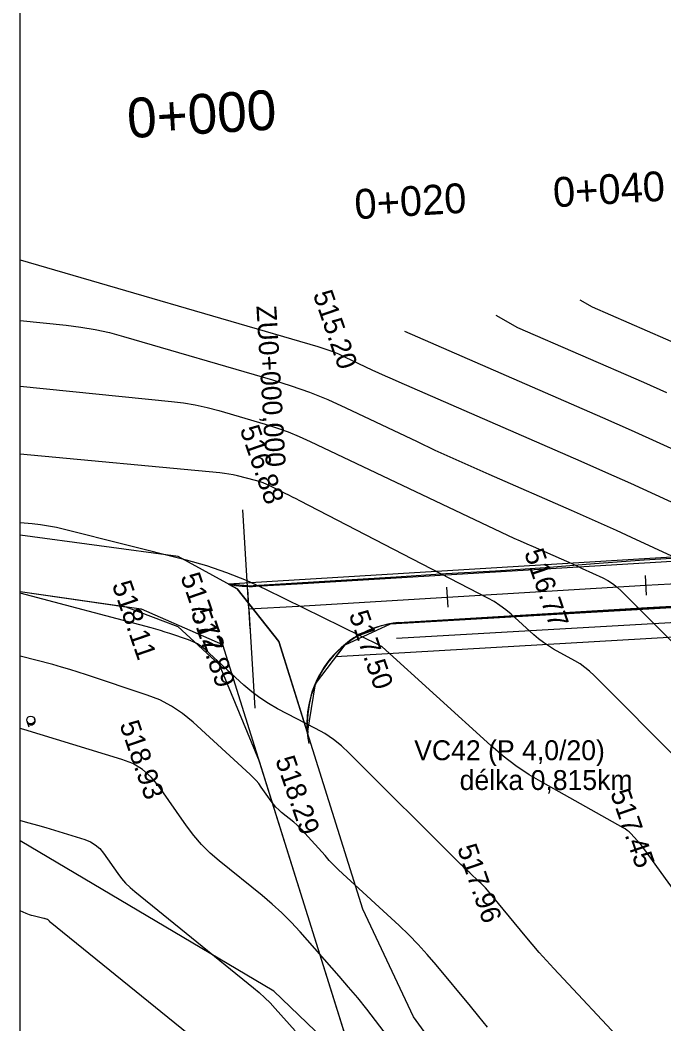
# Model space of a CAD drawing. Extents: x -636600 to -628587, y -1090963 to -1085869.
# Drawn here: x -629847.3 to -629782.5, y -1090868.7 to -1090767.7 of the extents above; entities that cross this region are included whole.
import ezdxf

# ---------------------------------------------------------------- set-up
doc = ezdxf.new("R2010")
doc.units = 0
for name, color, linetype in [('01_PARCELY_NÁVRH_PC', 7, 'Continuous'), ('06_ÚSES_IP_NAVRH', 7, 'Continuous'), ('08_LEGENDA_HV', 7, 'Continuous'), ('21', 7, 'Continuous'), ('42', 7, 'Continuous'), ('43', 7, 'Continuous'), ('Ex_Major Contours', 7, 'Continuous'), ('Ex_Minor Contours', 7, 'Continuous'), ('HEKTOMETRY100', 7, 'Continuous'), ('HEKTOMETRY20', 7, 'Continuous'), ('HL_BODY', 7, 'Continuous'), ('koty_vše', 7, 'Continuous'), ('POLOMERY', 7, 'Continuous'), ('popis', 7, 'Continuous'), ('situace_osa', 7, 'Continuous'), ('situace_těleso', 7, 'Continuous'), ('situace_vozovka', 7, 'Continuous')]:
    doc.layers.add(name, color=color, linetype=linetype)

msp = doc.modelspace()

# ---------------------------------------------------------------- linework, layer by layer
at = {"layer": '01_PARCELY_NÁVRH_PC'}
for points in [[(-629366.45, -1090806.54), (-629540.95, -1090811.44), (-629547.05, -1090811.34), (-629630.75, -1090804.21), (-629643.55, -1090804.77), (-629656.06, -1090806.87), (-629680.19, -1090814.27), (-629692.51, -1090816.32), (-629826.29, -1090824.45), (-629825.42, -1090824.93), (-629821.23, -1090830.23), (-629818.34, -1090839.45), (-629817.55, -1090834.47), (-629814.57, -1090830.54), (-629810, -1090828.44), (-629690.54, -1090821.5), (-629677.85, -1090819.12), (-629655.84, -1090812.08), (-629642.72, -1090809.88), (-629628.47, -1090809.45), (-629558.8, -1090815.77), (-629541.71, -1090816.24), (-629432.05, -1090813.18)], [(-629744.6, -1090962.82), (-629759.09, -1090922.57), (-629763.2, -1090915.17), (-629771.31, -1090905.23), (-629791.75, -1090887), (-629800.69, -1090877.61), (-629807.7, -1090867.98), (-629812.78, -1090857.14), (-629821.23, -1090830.23), (-629825.42, -1090824.93), (-629831.35, -1090821.66), (-629847.27, -1090819.51)], [(-629847.27, -1090825.18), (-629836.62, -1090826.73), (-629831.4, -1090828.72), (-629827.25, -1090832.52), (-629823.21, -1090842.26), (-629813.5, -1090873.3), (-629773.29, -1090911.83), (-629764.97, -1090924.29), (-629750.86, -1090962.82)]]:
    msp.add_lwpolyline(points, dxfattribs=at)
msp.add_lwpolyline([(-629815.5, -1090831.76), (-629814.57, -1090830.54), (-629810, -1090828.44), (-629690.54, -1090821.5), (-629677.85, -1090819.12), (-629655.84, -1090812.08), (-629642.72, -1090809.88), (-629628.47, -1090809.45), (-629558.8, -1090815.77), (-629551.1, -1090815.98), (-629546.74, -1090819.11), (-629558.97, -1090818.77), (-629628.56, -1090812.45), (-629642.43, -1090812.87), (-629655.13, -1090815), (-629677.12, -1090822.03), (-629690.18, -1090824.48)], close=True, dxfattribs=at)
at = {"layer": '06_ÚSES_IP_NAVRH'}
msp.add_lwpolyline([(-629809.39, -1090829.88), (-629689.14, -1090823.02), (-629677.01, -1090820.36), (-629655.14, -1090813.49), (-629637.21, -1090811.06), (-629627.89, -1090811.09), (-629550.85, -1090817.6)], dxfattribs=at)
at = {"layer": '08_LEGENDA_HV'}
msp.add_line((-629847.27, -1090962.82), (-629847.27, -1090665.82), dxfattribs=at)
at = {"layer": '21'}
for p, q in [((-629821.74, -1090865.4), (-629847.27, -1090850.26)), ((-629773.29, -1090911.83), (-629821.74, -1090865.4))]:
    msp.add_line(p, q, dxfattribs=at)
at = {"layer": '42'}
for p, q in [((-629847.27, -1090825.18), (-629835.09, -1090826.95)), ((-629835.09, -1090826.95), (-629826.89, -1090830.51)), ((-629826.89, -1090830.51), (-629814.27, -1090870.83))]:
    msp.add_line(p, q, dxfattribs=at)
at = {"layer": '43'}
for p, q in [((-629846.57, -1090838.25), (-629846.54, -1090838.34)), ((-629846.54, -1090838.34), (-629846.38, -1090838.81))]:
    msp.add_line(p, q, dxfattribs=at)
msp.add_circle((-629846.2, -1090838.12), 0.4, dxfattribs=at)
msp.add_arc((-629846.16, -1090838.21), 0.4, 188.7382, 26.2238, dxfattribs=at)
at = {"layer": 'Ex_Major Contours'}
for points in [[(-629808.6, -1090799.01), (-629788.68, -1090807.7), (-629785.79, -1090808.97), (-629782.91, -1090810.26), (-629780.03, -1090811.57)], [(-629775.18, -1090864), (-629784.52, -1090851.04), (-629784.66, -1090850.85), (-629784.82, -1090850.65), (-629784.98, -1090850.46), (-629785.15, -1090850.28), (-629785.82, -1090849.55), (-629786, -1090849.38), (-629786.19, -1090849.22), (-629786.39, -1090849.08), (-629786.6, -1090848.95), (-629794.66, -1090844.45), (-629796.05, -1090843.62), (-629797.39, -1090842.72), (-629798.67, -1090841.74), (-629799.9, -1090840.69), (-629810.84, -1090830.77), (-629810.86, -1090830.76), (-629810.88, -1090830.74), (-629810.9, -1090830.73), (-629810.92, -1090830.72), (-629811, -1090830.68), (-629811.02, -1090830.67), (-629811.04, -1090830.66), (-629811.06, -1090830.65), (-629811.09, -1090830.63), (-629822.55, -1090824.98), (-629824.49, -1090824.08), (-629826.47, -1090823.3), (-629828.49, -1090822.62), (-629830.54, -1090822.04), (-629842.8, -1090818.96), (-629843.6, -1090818.77), (-629844.42, -1090818.61), (-629845.23, -1090818.49), (-629846.05, -1090818.4), (-629847.27, -1090818.28)], [(-629824.45, -1090874.47), (-629844.23, -1090858.47), (-629844.26, -1090858.45), (-629844.28, -1090858.42), (-629844.3, -1090858.4), (-629844.32, -1090858.37), (-629844.4, -1090858.26), (-629844.42, -1090858.24), (-629844.44, -1090858.22), (-629844.47, -1090858.2), (-629844.5, -1090858.19), (-629844.71, -1090858.13), (-629844.75, -1090858.11), (-629844.8, -1090858.1), (-629844.84, -1090858.09), (-629844.89, -1090858.08), (-629845.94, -1090857.83), (-629846.12, -1090857.78), (-629846.31, -1090857.72), (-629846.49, -1090857.66), (-629846.67, -1090857.58), (-629847.27, -1090857.32)]]:
    msp.add_lwpolyline(points, dxfattribs=at)
at = {"layer": 'Ex_Minor Contours'}
for points in [[(-629847.27, -1090791.82), (-629817.31, -1090800.56), (-629816.6, -1090800.78), (-629815.91, -1090801.03), (-629815.22, -1090801.3), (-629814.55, -1090801.61), (-629811.87, -1090802.88), (-629811.2, -1090803.19), (-629810.53, -1090803.5), (-629809.85, -1090803.81), (-629809.17, -1090804.11), (-629790.87, -1090812.09), (-629788.36, -1090813.19), (-629785.87, -1090814.31), (-629783.37, -1090815.44), (-629780.89, -1090816.58)], [(-629780.45, -1090800.61), (-629789.67, -1090796.59), (-629790.91, -1090795.88)], [(-629799.42, -1090797.39), (-629797.22, -1090798.64), (-629784.57, -1090804.15), (-629782.25, -1090805.17)], [(-629847.27, -1090797.93), (-629842.63, -1090798.41), (-629841.16, -1090798.59), (-629839.71, -1090798.84), (-629838.27, -1090799.15), (-629836.85, -1090799.53), (-629821.89, -1090803.89), (-629820, -1090804.49), (-629818.14, -1090805.15), (-629816.3, -1090805.89), (-629814.5, -1090806.71), (-629807.33, -1090810.11), (-629805.53, -1090810.96), (-629803.73, -1090811.79), (-629801.92, -1090812.6), (-629800.11, -1090813.4), (-629791.84, -1090817.01), (-629790.33, -1090817.67), (-629788.82, -1090818.35), (-629787.31, -1090819.03), (-629785.81, -1090819.72), (-629779.5, -1090822.66)], [(-629847.27, -1090804.52), (-629832.04, -1090806.07), (-629830.84, -1090806.22), (-629829.64, -1090806.43), (-629828.46, -1090806.68), (-629827.29, -1090807), (-629822.62, -1090808.36), (-629821.46, -1090808.72), (-629820.31, -1090809.13), (-629819.19, -1090809.59), (-629818.08, -1090810.09), (-629798.23, -1090819.51), (-629797.59, -1090819.81), (-629796.95, -1090820.11), (-629796.3, -1090820.4), (-629795.66, -1090820.68), (-629792.82, -1090821.92), (-629792.3, -1090822.15), (-629791.77, -1090822.39), (-629791.25, -1090822.62), (-629790.73, -1090822.87), (-629788.64, -1090823.83), (-629788.13, -1090824.1), (-629787.66, -1090824.4), (-629787.21, -1090824.75), (-629786.79, -1090825.13), (-629776.22, -1090835.75)], [(-629780.67, -1090842.53), (-629789.53, -1090833.63), (-629789.98, -1090833.22), (-629790.45, -1090832.83), (-629790.94, -1090832.48), (-629791.46, -1090832.17), (-629793.6, -1090830.98), (-629794.12, -1090830.66), (-629794.63, -1090830.32), (-629795.11, -1090829.95), (-629795.57, -1090829.56), (-629797.87, -1090827.48), (-629798.41, -1090827.02), (-629798.99, -1090826.59), (-629799.58, -1090826.2), (-629800.21, -1090825.85), (-629819.13, -1090816.06), (-629819.49, -1090815.87), (-629819.86, -1090815.69), (-629820.22, -1090815.5), (-629820.59, -1090815.32), (-629822.07, -1090814.59), (-629822.44, -1090814.42), (-629822.82, -1090814.27), (-629823.21, -1090814.14), (-629823.6, -1090814.03), (-629825.4, -1090813.57), (-629825.84, -1090813.47), (-629826.27, -1090813.39), (-629826.72, -1090813.32), (-629827.16, -1090813.27), (-629847.27, -1090811.36)], [(-629786.31, -1090870.88), (-629793.58, -1090863.12), (-629794.32, -1090862.31), (-629795.05, -1090861.5), (-629795.77, -1090860.67), (-629796.47, -1090859.83), (-629800.25, -1090855.25), (-629800.46, -1090855.01), (-629800.67, -1090854.78), (-629800.88, -1090854.56), (-629801.11, -1090854.35), (-629802.03, -1090853.5), (-629802.25, -1090853.29), (-629802.48, -1090853.08), (-629802.7, -1090852.86), (-629802.93, -1090852.64), (-629814.15, -1090841.45), (-629814.92, -1090840.73), (-629815.75, -1090840.07), (-629816.62, -1090839.49), (-629817.54, -1090838.96), (-629821.37, -1090836.98), (-629822.27, -1090836.47), (-629823.14, -1090835.9), (-629823.97, -1090835.28), (-629824.75, -1090834.6), (-629828.64, -1090831.04), (-629829.02, -1090830.73), (-629829.42, -1090830.46), (-629829.85, -1090830.24), (-629830.31, -1090830.06), (-629832.19, -1090829.43), (-629832.66, -1090829.27), (-629833.14, -1090829.13), (-629833.61, -1090828.99), (-629834.09, -1090828.86), (-629847.27, -1090825.37)], [(-629800.26, -1090869.02), (-629801.11, -1090867.96), (-629801.97, -1090866.91), (-629805.42, -1090862.73), (-629806.3, -1090861.7), (-629807.21, -1090860.7), (-629808.16, -1090859.74), (-629809.14, -1090858.8), (-629814.81, -1090853.58), (-629815.27, -1090853.15), (-629815.73, -1090852.7), (-629816.16, -1090852.24), (-629816.59, -1090851.76), (-629818.61, -1090849.49), (-629818.87, -1090849.2), (-629819.15, -1090848.92), (-629819.44, -1090848.66), (-629819.74, -1090848.41), (-629820.96, -1090847.42), (-629821.25, -1090847.16), (-629821.53, -1090846.89), (-629821.78, -1090846.6), (-629822.02, -1090846.28), (-629823.01, -1090844.86), (-629823.26, -1090844.52), (-629823.53, -1090844.2), (-629823.81, -1090843.89), (-629824.11, -1090843.6), (-629829.87, -1090838.32), (-629830.92, -1090837.46), (-629832.03, -1090836.72), (-629833.22, -1090836.1), (-629834.48, -1090835.61), (-629840.57, -1090833.57), (-629841.41, -1090833.29), (-629842.26, -1090833.03), (-629843.11, -1090832.79), (-629843.96, -1090832.55), (-629847.27, -1090831.68)], [(-629800.44, -1090882.81), (-629811.52, -1090868.33), (-629812.4, -1090867.2), (-629813.3, -1090866.08), (-629814.22, -1090864.98), (-629815.16, -1090863.9), (-629819.1, -1090859.44), (-629820, -1090858.47), (-629820.94, -1090857.53), (-629821.92, -1090856.63), (-629822.93, -1090855.78), (-629827.25, -1090852.29), (-629828.16, -1090851.5), (-629829.01, -1090850.64), (-629829.8, -1090849.73), (-629830.53, -1090848.77), (-629833.32, -1090844.78), (-629834.07, -1090843.86), (-629834.95, -1090843.11), (-629835.93, -1090842.51), (-629837.04, -1090842.08), (-629846.9, -1090839.07), (-629847.27, -1090838.96)], [(-629847.27, -1090848.22), (-629847.24, -1090848.22), (-629846.38, -1090848.45), (-629845.52, -1090848.69), (-629844.67, -1090848.94), (-629840.77, -1090850.13), (-629840.2, -1090850.36), (-629839.7, -1090850.66), (-629839.25, -1090851.05), (-629838.86, -1090851.52), (-629837.43, -1090853.57), (-629837.05, -1090854.07), (-629836.65, -1090854.53), (-629836.21, -1090854.97), (-629835.74, -1090855.38), (-629823.77, -1090865.06), (-629823.2, -1090865.54), (-629822.64, -1090866.05), (-629822.11, -1090866.58), (-629821.6, -1090867.13), (-629819.61, -1090869.39)]]:
    msp.add_lwpolyline(points, dxfattribs=at)
at = {"layer": 'HEKTOMETRY100'}
msp.add_lwpolyline([(-629824.38, -1090824.96), (-629824.14, -1090828.95)], dxfattribs=at)
at = {"layer": 'HEKTOMETRY20'}
for points in [[(-629784.39, -1090823.57), (-629784.27, -1090825.57)], [(-629804.36, -1090824.76), (-629804.24, -1090826.76)]]:
    msp.add_lwpolyline(points, dxfattribs=at)
at = {"layer": 'HL_BODY'}
msp.add_lwpolyline([(-629824.26, -1090826.95), (-629824.86, -1090816.97)], dxfattribs=at)
at = {"layer": 'POLOMERY'}
msp.add_lwpolyline([(-629824.26, -1090826.95), (-629823.66, -1090836.94)], dxfattribs=at)
at = {"layer": 'situace_osa'}
msp.add_lwpolyline([(-629824.26, -1090826.95), (-629819.27, -1090826.66), (-629814.28, -1090826.36), (-629809.29, -1090826.06), (-629804.3, -1090825.76), (-629799.3, -1090825.46), (-629794.31, -1090825.16), (-629789.32, -1090824.87), (-629784.33, -1090824.57), (-629779.34, -1090824.27), (-629774.35, -1090823.97), (-629769.36, -1090823.67), (-629764.37, -1090823.37), (-629759.38, -1090823.08), (-629754.38, -1090822.78), (-629749.39, -1090822.48), (-629744.4, -1090822.18), (-629739.41, -1090821.88), (-629734.42, -1090821.58), (-629729.43, -1090821.29), (-629724.44, -1090820.99), (-629719.45, -1090820.69), (-629714.46, -1090820.39)], dxfattribs=at)
at = {"layer": 'situace_těleso'}
msp.add_line((-629824.4, -1090824.61), (-629826.29, -1090824.45), dxfattribs=at)
for points in [[(-629824.4, -1090824.61), (-629819.41, -1090824.31), (-629814.42, -1090824.01), (-629809.43, -1090823.7), (-629804.44, -1090823.39), (-629799.44, -1090823.12), (-629794.46, -1090822.77), (-629789.47, -1090822.37), (-629784.48, -1090822.02), (-629779.49, -1090821.7), (-629774.5, -1090821.37), (-629769.52, -1090821.05), (-629764.53, -1090820.72), (-629759.54, -1090820.4), (-629754.54, -1090820.12), (-629749.55, -1090819.82), (-629744.56, -1090819.52), (-629739.57, -1090819.22), (-629734.58, -1090818.92), (-629729.59, -1090818.62), (-629724.6, -1090818.32), (-629719.61, -1090817.98), (-629714.62, -1090817.69)], [(-629714.31, -1090822.77), (-629719.31, -1090823.03), (-629724.3, -1090823.29), (-629729.29, -1090823.59), (-629734.28, -1090823.88), (-629739.27, -1090824.18), (-629744.27, -1090824.48), (-629749.26, -1090824.78), (-629754.25, -1090825.07), (-629759.24, -1090825.37), (-629764.23, -1090825.65), (-629769.22, -1090825.96), (-629774.21, -1090826.27), (-629779.2, -1090826.58), (-629784.19, -1090826.89), (-629789.18, -1090827.22), (-629794.17, -1090827.5), (-629799.17, -1090827.77), (-629804.16, -1090828.08), (-629809.15, -1090828.38), (-629810, -1090828.44)]]:
    msp.add_lwpolyline(points, dxfattribs=at)
msp.add_arc((-629808.13, -1090838.51), 10.25, 100.5033, 185.2147, dxfattribs=at)
at = {"layer": 'situace_vozovka'}
for points in [[(-629823.55, -1090824.66), (-629819.4, -1090824.41), (-629814.41, -1090824.11), (-629809.42, -1090823.81), (-629804.43, -1090823.52), (-629799.44, -1090823.22), (-629794.45, -1090822.92), (-629789.46, -1090822.62), (-629784.47, -1090822.32), (-629779.47, -1090822.02), (-629774.48, -1090821.73), (-629769.49, -1090821.43), (-629764.5, -1090821.13), (-629759.51, -1090820.83), (-629754.52, -1090820.53), (-629749.53, -1090820.23), (-629744.54, -1090819.94), (-629739.55, -1090819.64), (-629734.55, -1090819.34), (-629729.56, -1090819.04), (-629724.57, -1090818.74), (-629719.58, -1090818.44), (-629714.59, -1090818.14)], [(-629809.19, -1090828.31), (-629804.16, -1090828.01), (-629799.17, -1090827.71), (-629794.18, -1090827.41), (-629789.19, -1090827.11), (-629784.2, -1090826.81), (-629779.21, -1090826.52), (-629774.21, -1090826.22), (-629769.22, -1090825.92), (-629764.23, -1090825.62), (-629759.24, -1090825.32), (-629754.25, -1090825.02), (-629749.26, -1090824.73), (-629744.27, -1090824.43), (-629739.28, -1090824.13), (-629734.29, -1090823.83), (-629729.3, -1090823.53), (-629724.3, -1090823.23), (-629719.31, -1090822.94), (-629714.32, -1090822.64)]]:
    msp.add_lwpolyline(points, dxfattribs=at)
for centre, start, end in [((-629824.16, -1090814.43), 258.0265, 273.421), ((-629808.17, -1090838.51), 95.7355, 191.0297)]:
    msp.add_arc(centre, 10.25, start, end, dxfattribs=at)

# ---------------------------------------------------------------- texts
at = {"layer": 'HEKTOMETRY100'}
msp.add_text('0+000', height=4, rotation=3.421, dxfattribs=at).set_placement((-629836.38, -1090779.59))
at = {"layer": 'HEKTOMETRY20'}
for s, p in [('0+040', (-629793.57, -1090786.55)), ('0+020', (-629813.54, -1090787.75))]:
    msp.add_text(s, height=3, rotation=3.421, dxfattribs=at).set_placement(p)
at = {"layer": 'HL_BODY'}
msp.add_text('ZU0+000,000', height=2, rotation=273.421, dxfattribs=at).set_placement((-629823.5, -1090796.47))
at = {"layer": 'koty_vše'}
for s, p in [('515.20', (-629817.83, -1090795.28)), ('516.88', (-629825.19, -1090808.86)), ('516.77', (-629796.58, -1090821.28)), ('517.72', (-629831.16, -1090823.69)), ('518.11', (-629838.05, -1090824.5)), ('517.89', (-629830.11, -1090827.3)), ('517.50', (-629814.22, -1090827.49)), ('518.93', (-629837.29, -1090838.56)), ('518.29', (-629821.62, -1090842.12)), ('517.45', (-629787.92, -1090845.45)), ('517.96', (-629803.32, -1090850.99))]:
    msp.add_text(s, height=2, rotation=289.043, dxfattribs=at).set_placement(p)
at = {"layer": 'popis'}
for s, p in [('VC42 (P 4,0/20)', (-629807.62, -1090842.16)), ('délka 0,815km', (-629803.05, -1090845.16))]:
    msp.add_text(s, height=2, dxfattribs=at).set_placement(p)

doc.saveas('drawing.dxf')
